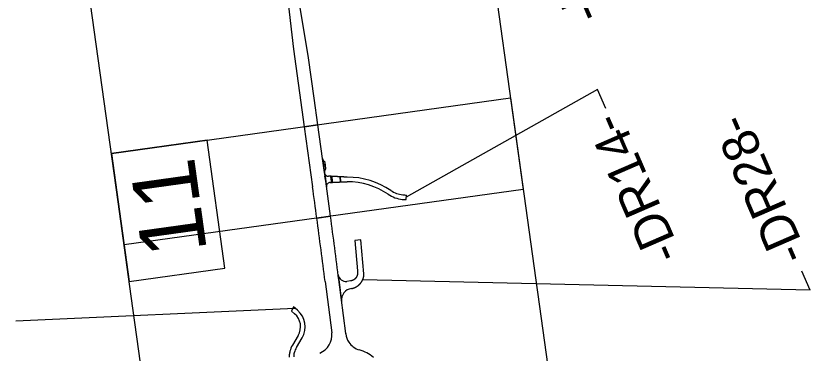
# Model space of a CAD drawing. Extents: x 442728 to 492797, y 479541 to 511293.
# Drawn here: x 477237 to 479306, y 497516 to 498393 of the extents above; entities that cross this region are included whole.
import ezdxf

# ---------------------------------------------------------------- set-up
doc = ezdxf.new("R2010")
doc.units = 0
for name, color, linetype in [('Prop DSN Text', 7, 'Continuous'), ('Prop Shade Light', 7, 'Continuous'), ('Sheet Plan Layout CELL', 7, 'Continuous')]:
    doc.layers.add(name, color=color, linetype=linetype)

msp = doc.modelspace()

# ---------------------------------------------------------------- linework, layer by layer
at = {"layer": 'Prop DSN Text'}
for p, q in [((478752.8250274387, 498201.64005766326), (478254.0247957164, 497921.5772783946)), ((478774.19041166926, 498152.36770687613), (478752.8250274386, 498201.6400576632)), ((479306.48513700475, 497679.88107260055), (479285.1197527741, 497729.1534233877)), ((479306.48513700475, 497679.8810726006), (478140.45610126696, 497706.4578380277)), ((477236.7227948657, 497599.91992059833), (477963.2893904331, 497632.7293691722))]:
    msp.add_line(p, q, dxfattribs=at)
at = {"layer": 'Prop Shade Light'}
for p, q in [((477932.7608186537, 498545.4004622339), (477959.8782098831, 498307.01279300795)), ((477999.36865778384, 498284.42438197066), (477970.783761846, 498457.9415775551)), ((477959.8782098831, 498307.01279300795), (477988.0009324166, 498104.9308886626)), ((478013.9862312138, 498179.38664701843), (477999.36865778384, 498284.42438197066)), ((478023.6573115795, 498109.89300766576), (478013.9862312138, 498179.3866470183)), ((477988.0009324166, 498104.93088866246), (478023.6573115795, 498109.89300766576)), ((478023.6573115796, 498109.89300766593), (477988.0009324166, 498104.9308886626)), ((477988.00093241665, 498104.93088866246), (478009.72596362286, 497948.82097885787)), ((478035.8617511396, 498022.1953679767), (478038.17141641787, 498005.5987686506)), ((478043.22192733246, 498005.5820556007), (478038.17141641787, 498005.5987686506)), ((478038.17141641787, 498005.5987686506), (478040.87402582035, 497986.17858434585)), ((478038.17141641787, 498005.5987686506), (478043.22192733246, 498005.5820556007)), ((478043.22192733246, 498005.5820556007), (478042.00772633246, 498014.30695946)), ((478044.6326003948, 497995.4453592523), (478043.22192733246, 498005.5820556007)), ((478028.6391128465, 497973.6260957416), (478028.6391128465, 497973.6260957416)), ((478042.27607234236, 497976.0208143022), (478042.2874103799, 497976.02240394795)), ((478056.10238539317, 497975.9287731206), (478050.9697131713, 497975.94575805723)), ((478058.1636482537, 497970.45513922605), (478058.50904436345, 497967.21773942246)), ((478058.50904436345, 497967.21773942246), (478058.8656204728, 497963.87370235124)), ((478060.8897568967, 497964.77767173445), (478060.6022296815, 497967.25961475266)), ((478100.12123274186, 497973.78309587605), (478096.0955480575, 497973.79641759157)), ((478058.8656204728, 497963.87370235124), (478059.24947197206, 497960.0782481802)), ((478083.11972435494, 497961.2199367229), (478082.7203716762, 497961.1739424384)), ((478096.0558381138, 497961.79648329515), (478100.08152279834, 497961.7831615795)), ((478253.6840010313, 497915.0862184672), (478254.3131604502, 497927.0697137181)), ((478020.951385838, 497867.0336350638), (478056.6080160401, 497871.995789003)), ((478135.56681732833, 497810.41633473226), (478119.6362068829, 497808.92782848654)), ((478119.6362068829, 497808.92782848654), (478127.0071028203, 497730.0414468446)), ((478143.841260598, 497722.4029915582), (478135.56681732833, 497810.41633473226)), ((478042.60128162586, 497702.38838057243), (478059.66821089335, 497568.69110192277)), ((478096.1965105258, 497566.8410370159), (478078.31150081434, 497706.94691602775)), ((478078.31150081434, 497706.94691602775), (478085.53999587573, 497650.3210225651)), ((478108.5122139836, 497703.6643331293), (478099.0475052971, 497702.4493477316)), ((477960.1192490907, 497635.874304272), (477954.57603911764, 497624.87667573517)), ((477970.46652614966, 497627.26868151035), (477960.1192490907, 497635.874304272)), ((477954.57603911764, 497624.87667573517), (477962.7933196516, 497618.0425283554)), ((477972.4276741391, 497561.6418795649), (477957.3800025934, 497536.4621527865)), ((477967.68076031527, 497530.30631081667), (477982.7284318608, 497555.486037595)), ((478096.1965105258, 497566.84103701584), (478096.3436237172, 497565.68859576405)), ((478096.3436237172, 497565.68859576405), (478096.1965105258, 497566.8410370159))]:
    msp.add_line(p, q, dxfattribs=at)
for points in [[(478042.28741037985, 497976.02240394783), (478040.87402582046, 497986.17858434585), (478035.8617511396, 498022.1953679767), (478023.6573115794, 498109.8930076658)], [(478041.0982603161, 497984.5672988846), (478042.2874119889, 497976.02239238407), (478046.0950026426, 497948.66212634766)], [(478059.23337658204, 497960.4230280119), (478058.8656204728, 497963.87370235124), (478058.50904436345, 497967.21773942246), (478058.1636482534, 497970.45513922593), (478057.8294321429, 497973.5859017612), (478057.5863874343, 497975.8496490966)], [(478057.5863874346, 497975.84964909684), (478057.8294321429, 497973.5859017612), (478058.1636482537, 497970.45513922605)], [(478059.61965357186, 497975.7412394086), (478059.73964803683, 497974.7054438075), (478060.0271752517, 497972.2235007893), (478060.31470246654, 497969.74155777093), (478060.6022296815, 497967.25961475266), (478060.88975689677, 497964.77767173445), (478061.1772841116, 497962.29572871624), (478061.4224223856, 497960.17968823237)], [(478060.6022296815, 497967.25961475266), (478060.3147024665, 497969.7415577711), (478060.0271752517, 497972.2235007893), (478059.73964803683, 497974.7054438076), (478059.619653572, 497975.74123940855)], [(478061.4224223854, 497960.1796882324), (478061.1772841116, 497962.29572871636), (478060.8897568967, 497964.77767173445)], [(478083.11972435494, 497961.2199367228), (478083.0342500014, 497961.9620813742), (478082.74075412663, 497964.44352410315), (478082.447258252, 497966.92496683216), (478082.1537623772, 497969.4064095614), (478081.86026650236, 497971.88785229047), (478081.5667706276, 497974.36929501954), (478081.54275480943, 497974.57234345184)], [(478081.5427548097, 497974.57234345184), (478081.8602665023, 497971.8878522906), (478082.1537623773, 497969.4064095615), (478082.4472582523, 497966.9249668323), (478082.7407541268, 497964.44352410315), (478083.0342500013, 497961.9620813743), (478083.11972435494, 497961.2199367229)], [(478056.0475312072, 497959.92886703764), (478056.04943880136, 497959.9288607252)], [(478059.249471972, 497960.0782481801), (478059.23337658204, 497960.4230280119)], [(478082.7203716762, 497961.1739424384), (478083.11972435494, 497961.2199367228)], [(478056.6080160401, 497871.995789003), (478021.10492347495, 497867.0550021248), (478020.95138583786, 497867.0336350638)], [(478111.49472584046, 497683.8776785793), (478111.4963749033, 497683.888216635)]]:
    msp.add_lwpolyline(points, dxfattribs=at)
for centre, radius, start, end in [((478045.76630090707, 498023.57373436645), 10.000000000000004, 187.92268114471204, 247.92268114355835), ((478050.7785755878, 497987.55695073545), 10, 127.92268114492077, 187.92268114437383), ((478051.0028047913, 497985.9457033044), 10.000000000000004, 187.92268114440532, 269.81039863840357), ((456237.54466289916, 494918.8959807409), 22018.000001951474, 7.707856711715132, 7.981110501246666), ((478099.43954537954, 497767.7842237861), 205.99999999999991, 56.245273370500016, 89.81039864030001), ((456237.54466289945, 494918.89598074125), 21982.000001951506, 7.7075048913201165, 7.922681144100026), ((478056.0144395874, 497949.9289217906), 10.000000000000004, 89.81039863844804, 187.27775770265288), ((478099.43954537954, 497767.7842237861), 193.99999999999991, 56.245273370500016, 89.81039864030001), ((478252.2402218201, 497996.4257626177), 81.00000000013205, 236.24527337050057, 263.94353818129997), ((478252.2402218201, 497996.4257626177), 69.00000000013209, 236.24527337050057, 263.94353818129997), ((478263.55190004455, 498103.0384567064), 176.21110299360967, 263.943538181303, 266.9946070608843), ((478263.55190004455, 498103.0384567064), 188.21110299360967, 263.943538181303, 266.9946070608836), ((456237.5446628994, 494918.89598074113), 21982.000001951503, 7.274664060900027, 7.707504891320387), ((456237.54466289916, 494918.8959807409), 22018.000001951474, 7.274664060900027, 7.707856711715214), ((478096.51164794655, 497722.28793204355), 20.000000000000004, 187.30823587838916, 277.28430342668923), ((456237.54466289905, 494918.895980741), 22018.000001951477, 7.274664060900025, 7.308235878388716), ((478115.2985118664, 497654.1198021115), 30.000000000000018, 97.2843034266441, 187.27466406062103), ((477934.6582291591, 497584.2133001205), 43.99999999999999, 329.13701335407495, 50.25038208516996), ((477934.6582291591, 497584.2133001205), 56, 329.13701335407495, 50.25038208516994), ((478010.07068424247, 497562.3598026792), 50.00000000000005, 291.5632961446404, 7.274664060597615), ((478145.941150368, 497572.0198950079), 50.000000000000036, 187.27466406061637, 213.1165968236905), ((478005.45020529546, 497507.73489026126), 56, 149.13701335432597, 166.70273625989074), ((478005.45020529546, 497507.73489026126), 43.999999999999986, 149.13701335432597, 166.7027362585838), ((478145.941150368, 497572.0198950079), 50.00000000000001, 213.11659682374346, 253.52423350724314), ((478100.5635852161, 497418.5895310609), 109.99999999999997, 51.549959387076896, 73.52423350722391)]:
    msp.add_arc(centre, radius, start, end, dxfattribs=at)
for points in [[(478057.58638743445, 497975.8496490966), (478057.1832816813, 497975.87114188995), (478056.64283353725, 497975.89995750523), (478056.10238539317, 497975.9287731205)], [(478059.61965357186, 497975.74123940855), (478059.34507425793, 497975.75587942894), (478058.80462611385, 497975.78469504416), (478058.26417796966, 497975.81351065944), (478057.7237298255, 497975.8423262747), (478057.58638743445, 497975.8496490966)], [(478069.43343961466, 497975.21798794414), (478069.073140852, 497975.2371983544), (478068.53269270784, 497975.2660139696), (478067.99224456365, 497975.29482958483), (478067.45179641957, 497975.3236452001), (478066.91134827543, 497975.35246081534), (478066.37090013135, 497975.3812764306), (478065.83045198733, 497975.41009204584), (478065.29000384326, 497975.4389076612), (478064.74955569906, 497975.4677232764), (478064.2091075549, 497975.4965388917), (478063.66865941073, 497975.52535450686), (478063.12821126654, 497975.55417012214), (478062.5877631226, 497975.5829857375), (478062.04731497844, 497975.61180135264), (478061.50686683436, 497975.6406169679), (478060.9664186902, 497975.66943258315), (478060.42597054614, 497975.6982481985), (478059.88552240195, 497975.72706381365), (478059.61965357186, 497975.74123940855)], [(478081.54275480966, 497974.5723434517), (478081.5034481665, 497974.5744392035), (478080.96300002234, 497974.6032548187), (478080.4225518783, 497974.632070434), (478079.8821037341, 497974.66088604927), (478079.34165559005, 497974.68970166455), (478078.80120744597, 497974.71851727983), (478078.2607593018, 497974.74733289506), (478077.72031115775, 497974.7761485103), (478077.1798630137, 497974.8049641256), (478076.6394148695, 497974.83377974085), (478076.09896672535, 497974.862595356), (478075.55851858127, 497974.8914109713), (478075.01807043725, 497974.9202265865), (478074.47762229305, 497974.94904220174), (478073.9371741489, 497974.97785781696), (478073.39672600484, 497975.0066734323), (478072.85627786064, 497975.0354890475), (478072.31582971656, 497975.0643046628), (478071.7753815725, 497975.09312027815), (478071.23493342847, 497975.12193589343), (478070.6944852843, 497975.1507515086), (478070.15403714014, 497975.1795671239), (478069.61358899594, 497975.2083827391), (478069.43343961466, 497975.21798794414)], [(478082.76449383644, 497974.5072027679), (478082.58434445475, 497974.51680797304), (478082.0438963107, 497974.5456235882), (478081.5427548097, 497974.57234345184)], [(478096.0955480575, 497973.79641759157), (478095.0146517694, 497973.85404882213), (478094.4742036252, 497973.88286443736), (478093.93375548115, 497973.91168005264), (478093.39330733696, 497973.9404956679), (478092.8528591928, 497973.9693112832), (478092.3124110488, 497973.9981268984), (478091.7719629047, 497974.0269425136), (478091.23151476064, 497974.0557581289), (478090.69106661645, 497974.0845737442), (478090.15061847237, 497974.1133893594), (478089.6101703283, 497974.14220497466), (478089.0697221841, 497974.1710205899), (478088.52927404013, 497974.1998362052), (478087.98882589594, 497974.22865182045), (478087.44837775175, 497974.25746743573), (478086.9079296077, 497974.286283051), (478086.36748146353, 497974.3150986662), (478085.8270333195, 497974.3439142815), (478085.28658517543, 497974.37272989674), (478084.7461370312, 497974.40154551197), (478084.20568888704, 497974.43036112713), (478083.66524074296, 497974.45917674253), (478083.12479259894, 497974.48799235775), (478082.76449383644, 497974.5072027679)], [(478056.04943880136, 497959.9288607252), (478056.5900658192, 497959.95409886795), (478057.13069283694, 497959.97933701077), (478057.6713198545, 497960.00457515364), (478058.21194687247, 497960.02981329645), (478058.7525738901, 497960.05505143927), (478059.249471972, 497960.07824818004)], [(478059.2494719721, 497960.07824818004), (478059.2932009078, 497960.08028958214), (478059.8338279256, 497960.105527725), (478060.37445494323, 497960.13076586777), (478060.915081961, 497960.15600401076), (478061.4224223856, 497960.1796882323)], [(478069.38490523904, 497960.5514015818), (478069.56511424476, 497960.55981429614), (478070.1057412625, 497960.58505243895), (478070.64636828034, 497960.6102905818), (478071.186995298, 497960.6355287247), (478071.72762231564, 497960.6607668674), (478072.2682493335, 497960.68600501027), (478072.8088763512, 497960.7112431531), (478073.34950336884, 497960.73648129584), (478073.8901303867, 497960.76171943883), (478074.4307574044, 497960.7869575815), (478074.9713844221, 497960.81219572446), (478075.51201143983, 497960.8374338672), (478076.0526384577, 497960.8626720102), (478076.5932654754, 497960.88791015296), (478077.133892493, 497960.9131482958), (478077.6745195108, 497960.9383864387), (478078.21514652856, 497960.96362458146), (478078.75577354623, 497960.9888627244), (478079.29640056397, 497961.01410086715), (478079.8370275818, 497961.03933901), (478080.37765459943, 497961.0645771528), (478080.9182816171, 497961.0898152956), (478081.45890863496, 497961.1150534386), (478081.9995356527, 497961.1402915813), (478082.54016267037, 497961.16552972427), (478082.72037167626, 497961.1739424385)], [(478082.72037167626, 497961.1739424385), (478083.0807896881, 497961.190767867), (478083.62141670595, 497961.21600600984), (478084.1620437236, 497961.24124415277), (478084.70267074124, 497961.2664822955), (478085.24329775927, 497961.2917204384), (478085.7839247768, 497961.3169585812), (478086.32455179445, 497961.342196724), (478086.8651788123, 497961.3674348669), (478087.40580583, 497961.39267300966), (478087.9464328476, 497961.4179111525), (478088.48705986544, 497961.44314929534), (478089.02768688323, 497961.4683874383), (478089.56831390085, 497961.49362558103), (478090.1089409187, 497961.51886372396), (478090.64956793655, 497961.5441018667), (478091.1901949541, 497961.5693400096), (478091.73082197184, 497961.5945781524), (478092.2714489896, 497961.6198162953), (478092.81207600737, 497961.64505443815), (478093.352703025, 497961.6702925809), (478093.8933300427, 497961.69553072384), (478094.43395706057, 497961.7207688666), (478094.97458407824, 497961.74600700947), (478096.0558381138, 497961.7964832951)], [(478126.24024715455, 497718.0579780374), (478126.118280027, 497717.6891353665), (478125.95767447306, 497717.23474470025), (478125.78705995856, 497716.78466661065), (478125.60654916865, 497716.3391211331), (478125.41625961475, 497715.8983254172), (478125.2163135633, 497715.46249362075), (478125.00683795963, 497715.0318368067), (478124.78796435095, 497714.6065628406), (478124.559828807, 497714.1868762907), (478124.32257183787, 497713.77297832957), (478124.07633831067, 497713.36506663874), (478123.8212773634, 497712.96333531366), (478123.5575423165, 497712.5679747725), (478123.28529058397, 497712.17917166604), (478123.0046835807, 497711.79710879), (478122.71588662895, 497711.4219649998), (478122.419068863, 497711.05391512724), (478122.114403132, 497710.69312989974), (478121.80206590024, 497710.3397758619), (478121.4822371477, 497709.9940152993), (478121.1551002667, 497709.6560061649), (478120.8208419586, 497709.32590200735), (478120.47965212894, 497709.00385190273), (478120.1317237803, 497708.69000038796), (478119.77725290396, 497708.384487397), (478119.5394604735, 497708.18719306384)], [(478127.0071028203, 497730.0414468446), (478127.0790016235, 497728.6909273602), (478127.114951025, 497728.015667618), (478127.1509004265, 497727.3404078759), (478127.18684982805, 497726.66514813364), (478127.2227992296, 497725.9898883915), (478127.2545052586, 497725.3568898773), (478127.2651852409, 497724.86534282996), (478127.2647595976, 497724.37428773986), (478127.2532559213, 497723.8839751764), (478127.2307074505, 497723.3946547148), (478127.19715303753, 497722.9065748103), (478127.1526371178, 497722.4199826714), (478127.09720967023, 497721.9351241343), (478127.0309261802, 497721.4522435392), (478126.9538475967, 497720.97158360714), (478126.86604028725, 497720.4933853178), (478126.76757599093, 497720.0178877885), (478126.65853176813, 497719.5453281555), (478126.53898994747, 497719.0759414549), (478126.4090380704, 497718.60996050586), (478126.2687688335, 497718.1476157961), (478126.2402471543, 497718.0579780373)], [(478134.6796075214, 497697.27414784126), (478134.89717290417, 497697.5342776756), (478135.4524812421, 497698.21967643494), (478135.99182612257, 497698.91693742), (478136.5149551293, 497699.62568951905), (478137.0216244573, 497700.345556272), (478137.5115990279, 497701.07615607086), (478137.98465259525, 497701.81710236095), (478138.44056785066, 497702.56800384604), (478138.8791365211, 497703.32846469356), (478139.3001594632, 497704.0980847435), (478139.703446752, 497704.8764597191), (478140.0888177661, 497705.6631814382), (478140.45610126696, 497706.4578380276), (478140.80513547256, 497707.26001413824), (478141.1357681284, 497708.06929116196), (478141.44785657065, 497708.88524745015), (478141.74126778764, 497709.70745853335), (478142.01587847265, 497710.5354973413), (478142.27157507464, 497711.368934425), (478142.5082538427, 497712.20733817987), (478142.7258208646, 497713.05027506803), (478142.924192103, 497713.89730984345), (478143.1032934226, 497714.7480057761), (478143.2630606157, 497715.601924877), (478143.4034394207, 497716.45862812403), (478143.52438553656, 497717.3176756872), (478143.62586463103, 497718.1786271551), (478143.7078523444, 497719.0410417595), (478143.7703342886, 497719.9044786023), (478143.81330604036, 497720.7684968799), (478143.8367731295, 497721.6326561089), (478143.841260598, 497722.4029915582)], [(478119.5394604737, 497708.1871930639), (478119.416438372, 497708.08744819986), (478119.04948182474, 497707.7990133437), (478118.6765875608, 497707.5193085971), (478118.2979624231, 497707.2484548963), (478117.9138156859, 497706.986568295), (478117.5243589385, 497706.73375991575), (478117.1298059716, 497706.49013590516), (478116.7303726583, 497706.2557973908), (478116.32627683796, 497706.0308404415), (478115.917738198, 497705.8153560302), (478115.5049781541, 497705.6094299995), (478115.088219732, 497705.41314302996), (478114.6676874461, 497705.22657061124), (478114.2436071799, 497705.04978301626), (478113.8162060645, 497704.88284527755), (478113.38571235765, 497704.725817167), (478112.9523553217, 497704.5787531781), (478112.5163651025, 497704.44170251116), (478112.07797260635, 497704.3147090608), (478111.63740937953, 497704.19781140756), (478111.1949074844, 497704.09104281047), (478110.7506993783, 497703.99443120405), (478110.3050177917, 497703.907999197), (478109.8580956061, 497703.8317640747), (478109.41016573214, 497703.76573780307), (478108.96146098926, 497703.7099270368), (478108.5122139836, 497703.6643331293)], [(478111.4963749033, 497683.88821663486), (478112.3809684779, 497684.059285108), (478113.26088665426, 497684.250120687), (478114.13568810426, 497684.4605996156), (478115.0049347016, 497684.6905882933), (478115.86819174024, 497684.9399433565), (478116.7250281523, 497685.20851176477), (478117.5750167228, 497685.49613089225), (478118.417734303, 497685.80262862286), (478119.252762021, 497686.1278234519), (478120.0796854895, 497686.4715245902), (478120.8980950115, 497686.83353207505), (478121.7075857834, 497687.213636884), (478122.50775809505, 497687.61162105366), (478123.29821752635, 497688.0272578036), (478124.07857514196, 497688.4603116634), (478124.8484476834, 497688.91053860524), (478125.60745775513, 497689.3776861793), (478126.35523401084, 497689.8614936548), (478127.09141133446, 497690.36169216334), (478127.81563101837, 497690.8780048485), (478128.5275409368, 497691.41014701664), (478129.2267957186, 497691.9578262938), (478129.9130569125, 497692.520742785), (478130.58599315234, 497693.09858923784), (478131.24528031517, 497693.69105120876), (478131.8906016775, 497694.2978072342), (478132.52164806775, 497694.91852900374), (478133.1381180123, 497695.55288153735), (478133.7397178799, 497696.20052336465), (478134.32616202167, 497696.86110670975), (478134.6796075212, 497697.2741478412)], [(477950.95157324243, 497520.6150728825), (477950.63298156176, 497519.4450976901), (477950.4831003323, 497518.8571664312), (477950.33952735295, 497518.2673625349), (477950.202285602, 497517.67575371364), (477950.0713973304, 497517.08240795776), (477949.9468840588, 497516.4873935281), (477949.8287665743, 497515.89077894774), (477949.7170649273, 497515.2926329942), (477949.6117984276, 497514.6930246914), (477949.5129856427, 497514.0920233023), (477949.4206443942, 497513.4896983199), (477949.3347917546, 497512.8861194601), (477949.2554440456, 497512.28135665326), (477949.18261683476, 497511.67548003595), (477949.11632493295, 497511.0685599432), (477949.05658239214, 497510.4606668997), (477949.0034025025, 497509.85187161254), (477948.9567977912, 497509.24224496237), (477948.91678001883, 497508.63185799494), (477948.8833601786, 497508.02078191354), (477948.8565484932, 497507.4090880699), (477948.83635441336, 497506.7968479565), (477948.82278661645, 497506.1841331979), (477948.8160172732, 497505.5978157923)], [(477962.12680682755, 497506.41322588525), (477962.11510054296, 497506.54814678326), (477962.07778015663, 497507.01624687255), (477962.04551913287, 497507.48501522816), (477962.01832755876, 497507.9543971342), (477961.99621492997, 497508.4243377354), (477961.97919014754, 497508.89478204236), (477961.9672615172, 497509.36567493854), (477961.9604367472, 497509.83696118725), (477961.9587229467, 497510.3085854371), (477961.96212662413, 497510.780492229), (477961.97065368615, 497511.2526260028), (477961.9843094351, 497511.7249311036), (477962.0030985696, 497512.1973517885), (477962.0270251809, 497512.6698322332), (477962.05609275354, 497513.14231653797), (477962.0903041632, 497513.6147487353), (477962.1296616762, 497514.0870727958), (477962.17416694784, 497514.55923263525), (477962.2238210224, 497515.0311721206), (477962.27862433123, 497515.5028350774), (477962.3385766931, 497515.97416529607), (477962.40367731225, 497516.4451065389), (477962.47392477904, 497516.91560254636), (477962.62985153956, 497517.85503374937)]]:
    msp.add_spline(points, degree=3, dxfattribs=at)
msp.add_open_spline([(478061.4224223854, 497960.1796882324), (478061.4335179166, 497960.18020620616), (478061.4446134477, 497960.1807241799), (478061.45570897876, 497960.1812421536), (478061.6359179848, 497960.1896548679), (478061.8161269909, 497960.19806758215), (478061.9963359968, 497960.20648029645), (478062.17654500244, 497960.21489301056), (478062.35675400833, 497960.22330572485), (478062.5369630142, 497960.2317184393), (478062.7171720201, 497960.2401311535), (478062.89738102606, 497960.2485438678), (478063.0775900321, 497960.25695658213), (478063.25779903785, 497960.26536929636), (478063.4380080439, 497960.27378201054), (478063.6182170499, 497960.282194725), (478063.7984260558, 497960.29060743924), (478063.97863506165, 497960.2990201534), (478064.1588440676, 497960.3074328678), (478064.3390530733, 497960.3158455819), (478064.5192620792, 497960.3242582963), (478064.6994710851, 497960.3326710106), (478064.87968009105, 497960.3410837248), (478065.0598890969, 497960.3494964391), (478065.24009810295, 497960.35790915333), (478065.42030710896, 497960.36632186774), (478065.60051611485, 497960.374734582), (478065.7807251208, 497960.38314729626), (478065.9609341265, 497960.39156001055), (478066.14114313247, 497960.39997272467), (478066.32135213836, 497960.4083854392), (478066.50156114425, 497960.4167981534), (478066.6817701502, 497960.42521086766), (478066.8619791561, 497960.43362358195), (478067.0421881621, 497960.44203629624), (478067.22239716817, 497960.4504490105), (478067.40260617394, 497960.45886172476), (478067.58281517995, 497960.4672744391), (478067.76302418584, 497960.4756871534), (478067.9432331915, 497960.48409986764), (478068.12344219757, 497960.4925125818), (478068.30365120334, 497960.50092529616), (478068.48386020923, 497960.50933801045), (478068.6640692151, 497960.5177507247), (478068.8442782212, 497960.5261634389), (478069.0244872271, 497960.53457615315), (478069.1446265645, 497960.5401846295), (478069.26476590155, 497960.5457931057), (478069.3849052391, 497960.5514015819)], degree=3, dxfattribs=at)
at = {"layer": 'Sheet Plan Layout CELL'}
for points in [[(478558.9219758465, 497941.9002970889), (477518.8712955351, 497797.1616734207), (477363.8073222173, 498911.4073870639), (477363.8679953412, 498911.41583063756), (477312.1837148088, 499282.80440519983), (478352.1737219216, 499427.5345852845)], [(478732.56623871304, 496694.1418954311), (477692.5155584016, 496549.40327176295), (477537.45158508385, 497663.6489854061), (477537.5122582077, 497663.6574289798), (477485.82797767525, 498035.0460035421), (478525.8179847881, 498179.77618362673)], [(477781.5407273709, 497737.2112818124), (477735.29240010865, 498069.74153061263), (477485.82797767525, 498035.0460035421), (477532.0763049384, 497702.51575474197)]]:
    msp.add_lwpolyline(points, close=True, dxfattribs=at)

# ---------------------------------------------------------------- texts
at = {"layer": 'Prop DSN Text'}
for s, p in [('-DR15- ', (478768.89888943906, 498398.29403114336)), ('-DR14- ', (478972.6102381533, 497773.0415742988)), ('-DR28- ', (479301.23964800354, 497770.4199450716))]:
    msp.add_text(s, height=94.91812685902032, rotation=113.44242897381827, dxfattribs=at).set_placement(p)
at = {"layer": 'Sheet Plan Layout CELL'}
msp.add_text('11', height=168.74333799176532, rotation=97.91790848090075, dxfattribs=at).set_placement((477735.0220222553, 497781.00157405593))

doc.saveas('drawing.dxf')
